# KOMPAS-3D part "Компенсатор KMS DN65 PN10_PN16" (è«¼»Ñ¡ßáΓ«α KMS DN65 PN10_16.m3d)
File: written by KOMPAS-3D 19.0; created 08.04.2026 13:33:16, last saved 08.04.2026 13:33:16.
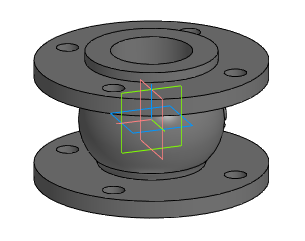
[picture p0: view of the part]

Document properties: Автор: Энергия; Полное имя файла: Z:\3.Личные\kachalov\3d для проектировщиков\7.1 Компенсатор\stp_Компенсатор KSM\Компенсатор KMS DN65 PN10_16.m3d

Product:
- Part/product: Компенсатор KMS DN65 PN10_PN16

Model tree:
1. Операция без истории:1  (labels: Компенсатор KMS DN65 PN10_PN16)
